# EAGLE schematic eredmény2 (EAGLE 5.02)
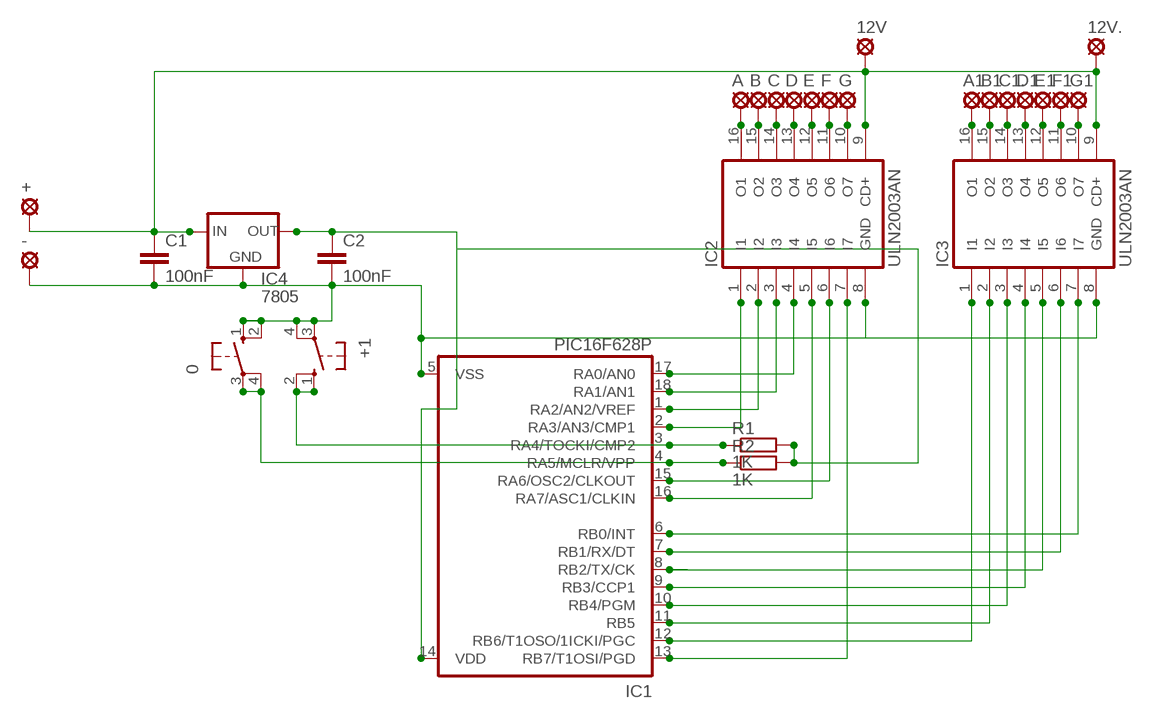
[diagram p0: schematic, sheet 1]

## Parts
0  10-XX  [B3F-10XX]
12V  MCS08  [MCS08]
12V.  MCS08  [MCS08]
+  MCS08  [MCS08]
+1  10-XX  [B3F-10XX]
-  MCS08  [MCS08]
A  MCS08  [MCS08]
A1  MCS08  [MCS08]
B  MCS08  [MCS08]
B1  MCS08  [MCS08]
C  MCS08  [MCS08]
C1  100nF  C-EU050-025X075  [C050-025X075]
C1.  MCS08  [MCS08]
C2  100nF  C-EU050-025X075  [C050-025X075]
D  MCS08  [MCS08]
D1  MCS08  [MCS08]
E  MCS08  [MCS08]
E1  MCS08  [MCS08]
F  MCS08  [MCS08]
F1  MCS08  [MCS08]
G  MCS08  [MCS08]
G1  MCS08  [MCS08]
IC1  PIC16F628P  [DIL18]
IC2  ULN2003AN  [DIL16]
IC3  ULN2003AN  [DIL16]
IC4  7805  78LXX  [78LXX]
R1  1K  R-EU_0207/10  [0207/10]
R2  1K  R-EU_0207/10  [0207/10]

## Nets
GND: 0.1(S) 0.2(S1) +1.3(P) +1.4(P1) -.MP C1.2 C2.2 IC1.5(VSS) IC2.8(GND) IC3.8(GND) IC4.GND
N$1: IC1.17(RA0/AN0) IC2.4(I4)
N$2: IC1.18(RA1/AN1) IC2.3(I3)
N$3: IC1.1(RA2/AN2/VREF) IC2.2(I2)
N$4: IC1.15(RA6/OSC2/CLKOUT) IC2.6(I6)
N$5: +1.1(S) +1.2(S1) IC1.3(RA4/TOCKI/CMP2) R1.1
N$6: 0.3(P) 0.4(P1) IC1.4(RA5/MCLR/VPP) R2.1
N$7: IC1.6(RB0/INT) IC3.7(I7)
N$8: IC1.8(RB2/TX/CK) IC3.5(I5)
N$9: IC1.7(RB1/RX/DT) IC3.6(I6)
N$10: C2.1 IC1.14(VDD) IC4.OUT R1.2 R2.2
N$11: IC1.10(RB4/PGM) IC3.3(I3)
N$12: IC1.11(RB5) IC3.2(I2)
N$13: IC1.12(RB6/T1OSO/1ICKI/PGC) IC3.1(I1)
N$16: IC1.13(RB7/T1OSI/PGD) IC2.7(I7)
N$17: IC1.16(RA7/ASC1/CLKIN) IC2.5(I5)
N$19: IC1.9(RB3/CCP1) IC3.4(I4)
N$21: IC1.2(RA3/AN3/CMP1) IC2.1(I1)
N$35: 12V..MP 12V.MP +.MP C1.1 IC2.9(CD+) IC3.9(CD+) IC4.IN
N$36: G1.MP IC3.10(O7)
N$37: F1.MP IC3.11(O6)
N$38: E1.MP IC3.12(O5)
N$39: D1.MP IC3.13(O4)
N$40: C1..MP IC3.14(O3)
N$41: B1.MP IC3.15(O2)
N$42: A1.MP IC3.16(O1)
N$44: G.MP IC2.10(O7)
N$45: F.MP IC2.11(O6)
N$46: E.MP IC2.12(O5)
N$47: D.MP IC2.13(O4)
N$48: C.MP IC2.14(O3)
N$49: B.MP IC2.15(O2)
N$50: A.MP IC2.16(O1)

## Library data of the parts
0 +1 = switch-omron:10-XX: OMRON SWITCH
12V 12V. + - A A1 B B1 C C1. D D1 E E1 F F1 G G1 = solpad:MCS08: SOLDER PAD
C1 C2 = rcl:C-EU: CAPACITOR, European symbol
IC1 = microchip:PIC16*F62: FLASH-Based 8-Bit CMOS Microcontroller Source: http://ww1.microchip.com/downloads/en/DeviceDoc/40300C.pdf
IC2 IC3 = uln-udn:ULN2003A: DRIVER ARRAY
IC4 = v-reg:78LXX: VOLTAGE REGULATOR
R1 R2 = rcl:R-EU_: RESISTOR, European symbol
